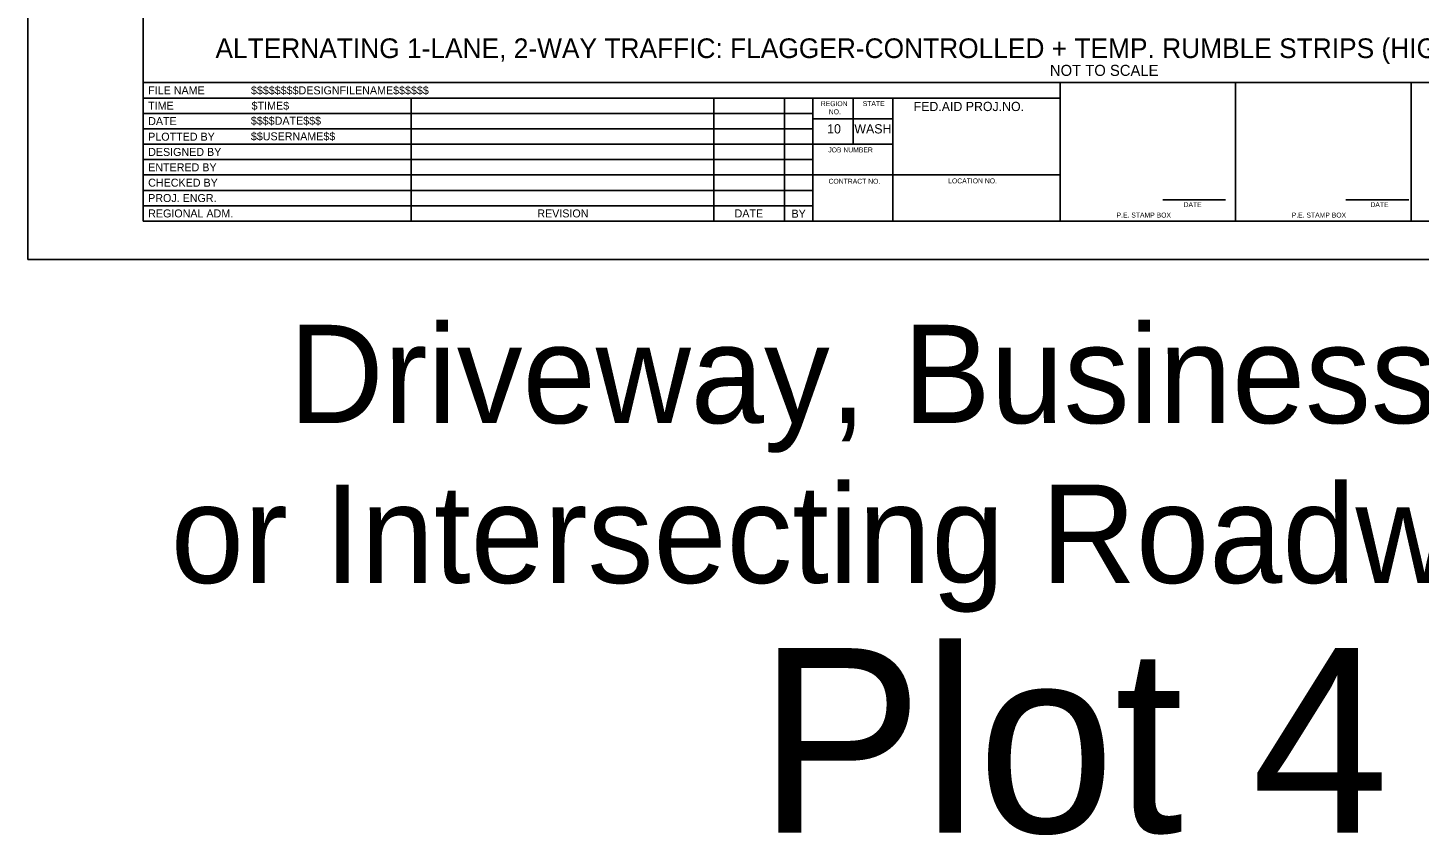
# Model space of a CAD drawing. Extents: x 99999.1 to 100095.7, y 99995 to 100010.7.
# Drawn here: x 100059.06 to 100070.38, y 99995.01 to 100001.57 of the extents above; entities that cross this region are included whole.
import ezdxf

# ---------------------------------------------------------------- set-up
doc = ezdxf.new("R2010")
doc.units = 0
for name, color, linetype in [('SH_DE_DetailHeading1Text', 7, 'Continuous'), ('SH_GI_PlotLimits', 7, 'Continuous'), ('SH_GI_SheetBorder', 7, 'Continuous'), ('SH_GI_SheetLocationText', 7, 'Continuous'), ('SH_GI_SheetTextInCells', 7, 'Continuous'), ('SH_GI_TitleBlockText', 7, 'Continuous')]:
    doc.layers.add(name, color=color, linetype=linetype)

msp = doc.modelspace()

# ---------------------------------------------------------------- linework, layer by layer
at = {"layer": 'SH_GI_PlotLimits'}
msp.add_lwpolyline([(100059.062, 99999.687), (100076.062, 99999.687), (100076.062, 100010.687), (100059.062, 100010.687)], close=True, dxfattribs=at)
at = {"layer": 'SH_GI_SheetBorder'}
for p, q in [((100060, 100010.375), (100060, 100000)), ((100060, 100001.126), (100075.75, 100001.126)), ((100067.457, 100000), (100067.457, 100001.126)), ((100068.883, 100000), (100068.883, 100001.126)), ((100070.309, 100001.126), (100070.309, 100000)), ((100060, 100001.001), (100067.457, 100001.001)), ((100062.179, 100001.001), (100062.179, 100000)), ((100064.641, 100001.001), (100064.641, 100000)), ((100065.216, 100001.001), (100065.216, 100000)), ((100065.445, 100001.001), (100065.445, 100000)), ((100065.772, 100000.625), (100065.772, 100001.001)), ((100066.096, 100000), (100066.096, 100001.001)), ((100060, 100000.876), (100062.182, 100000.876)), ((100062.182, 100000.876), (100065.447, 100000.876)), ((100066.096, 100000.831), (100065.447, 100000.831)), ((100060, 100000.751), (100062.182, 100000.751)), ((100062.182, 100000.751), (100065.447, 100000.751)), ((100060, 100000.625), (100065.447, 100000.625)), ((100066.096, 100000.625), (100065.447, 100000.625)), ((100060, 100000.5), (100065.447, 100000.5)), ((100060, 100000.375), (100065.447, 100000.375)), ((100067.457, 100000.375), (100065.447, 100000.375)), ((100060, 100000.25), (100065.447, 100000.25)), ((100060, 100000.125), (100065.447, 100000.125)), ((100068.29, 100000.173), (100068.802, 100000.173)), ((100069.78, 100000.173), (100070.291, 100000.173)), ((100060, 100000), (100075.75, 100000))]:
    msp.add_line(p, q, dxfattribs=at)

# ---------------------------------------------------------------- texts
at = {"layer": 'SH_DE_DetailHeading1Text'}
for s, height, p in [('ALTERNATING 1-LANE, 2-WAY TRAFFIC: FLAGGER-CONTROLLED + TEMP. RUMBLE STRIPS (HIGH VOLUME 45+ MPH HIGHWAYS)', 0.16, (100060.588, 100001.326)), ('NOT TO SCALE', 0.09, (100067.373, 100001.181))]:
    msp.add_text(s, height=height, rotation=360, dxfattribs=at).set_placement(p)
at = {"layer": 'SH_GI_SheetLocationText'}
for s, height, p in [('Driveway, Business Access,', 0.8, (100061.184, 99998.357)), ('or Intersecting Roadway Details', 0.8, (100060.225, 99997.057)), ('Plot 4', 1.5, (100065.001, 99995.027))]:
    msp.add_text(s, height=height, dxfattribs=at).set_placement(p)
at = {"layer": 'SH_GI_SheetTextInCells'}
for s, height, p in [('FILE NAME', 0.0651, (100060.041, 100001.031)), ('TIME', 0.0651, (100060.041, 100000.906)), ('REGION', 0.04, (100065.51, 100000.935)), ('NO.', 0.04, (100065.575, 100000.869)), ('STATE', 0.04, (100065.851, 100000.936)), ('FED.AID PROJ.NO.', 0.07506, (100066.265, 100000.895)), ('DATE', 0.0651, (100060.041, 100000.781)), ('10', 0.0751, (100065.562, 100000.713)), ('WASH', 0.0751, (100065.783, 100000.713)), ('PLOTTED BY', 0.0651, (100060.041, 100000.654)), ('DESIGNED BY', 0.06505, (100060.041, 100000.53)), ('JOB NUMBER', 0.04, (100065.571, 100000.559)), ('ENTERED BY', 0.0651, (100060.041, 100000.405)), ('CHECKED BY', 0.0651, (100060.041, 100000.28)), ('CONTRACT NO.', 0.04003, (100065.573, 100000.304)), ('LOCATION NO.', 0.04003, (100066.546, 100000.307)), ('PROJ. ENGR.', 0.06505, (100060.041, 100000.155)), ('REGIONAL ADM.', 0.06505, (100060.041, 100000.03)), ('REVISION', 0.0651, (100063.205, 100000.03)), ('DATE', 0.04, (100068.46, 100000.114)), ('DATE', 0.04, (100069.979, 100000.114)), ('DATE', 0.0651, (100064.809, 100000.03)), ('BY', 0.0651, (100065.272, 100000.028)), ('P.E. STAMP BOX', 0.04003, (100067.915, 100000.029)), ('P.E. STAMP BOX', 0.04003, (100069.339, 100000.029))]:
    msp.add_text(s, height=height, dxfattribs=at).set_placement(p)
at = {"layer": 'SH_GI_TitleBlockText'}
for s, height, p in [('$$$$$$$$DESIGNFILENAME$$$$$$', 0.06505, (100060.877, 100001.031)), ('$TIME$', 0.0651, (100060.882, 100000.906)), ('$$$$DATE$$$', 0.06505, (100060.876, 100000.784)), ('$$USERNAME$$', 0.06505, (100060.876, 100000.657))]:
    msp.add_text(s, height=height, dxfattribs=at).set_placement(p)

doc.saveas('drawing.dxf')
